Omron CX-Programmer project 新工程 (CX-Programmer 2.1)

# PLC hlp2b: C200H CPU01
; HLP2A数显表PLC程序

## Global symbols (name address type ; comment)
1.10 BOOL  ; SDA输出
1.11 BOOL  ; SCK输出
200.00 BOOL  ; 时钟脉冲
211 CHANNEL  ; 待显示数据送入该通道

## Program 新程序1 (no task)

### Section 段1

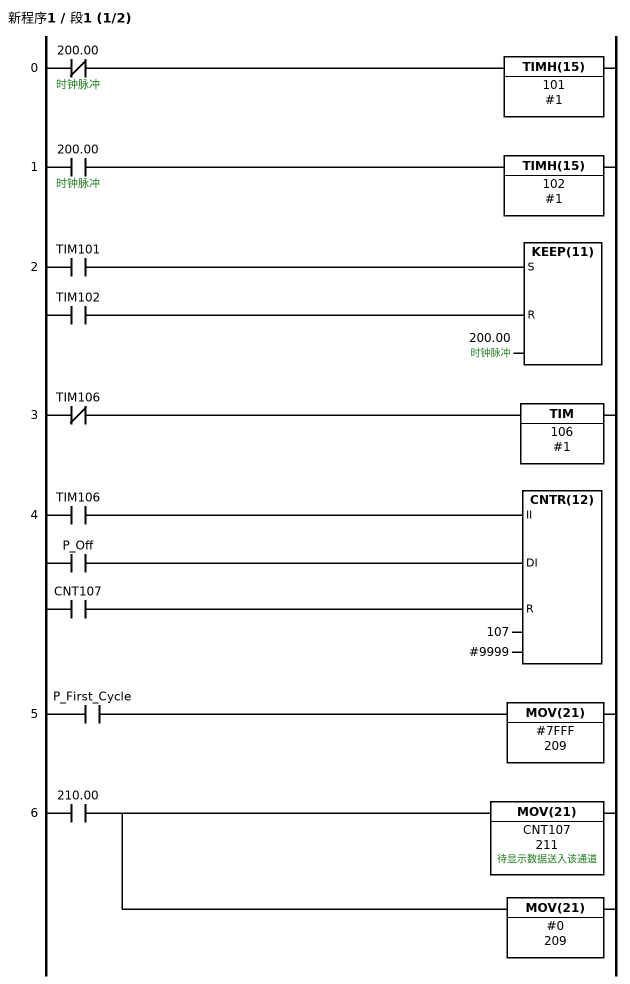
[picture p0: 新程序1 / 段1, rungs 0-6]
; rung 0
LDNOT 200.00  ; 时钟脉冲
TIMH(15) 101 #1
; rung 1
LD 200.00  ; 时钟脉冲
TIMH(15) 102 #1
; rung 2
LD TIM101
LD TIM102
KEEP(11) 200.00  ; 时钟脉冲
; rung 3
LDNOT TIM106
TIM 106 #1
; rung 4
LD TIM106
LD P_Off
LD CNT107
CNTR(12) 107 #9999
; rung 5
LD P_First_Cycle
MOV(21) #7FFF 209
; rung 6
LD 210.00
MOV(21) CNT107 211  ; 待显示数据送入该通道
MOV(21) #0 209

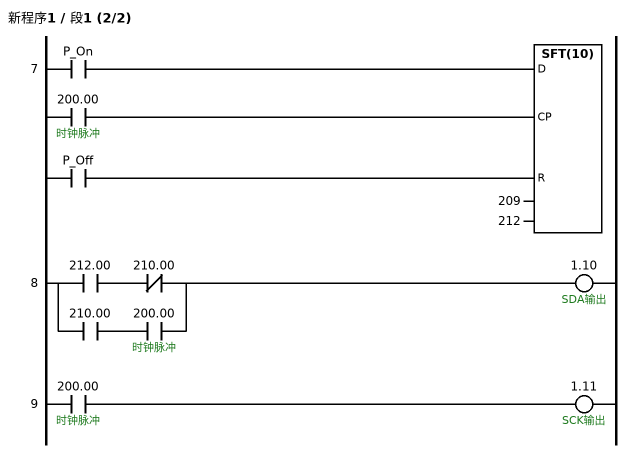
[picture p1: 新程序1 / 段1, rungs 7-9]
; rung 7
LD P_On
LD 200.00  ; 时钟脉冲
LD P_Off
SFT(10) 209 212
; rung 8
LD 212.00
ANDNOT 210.00
LD 210.00
AND 200.00  ; 时钟脉冲
ORLD
OUT 1.10  ; SDA输出
; rung 9
LD 200.00  ; 时钟脉冲
OUT 1.11  ; SCK输出
; rung 10
END(01)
